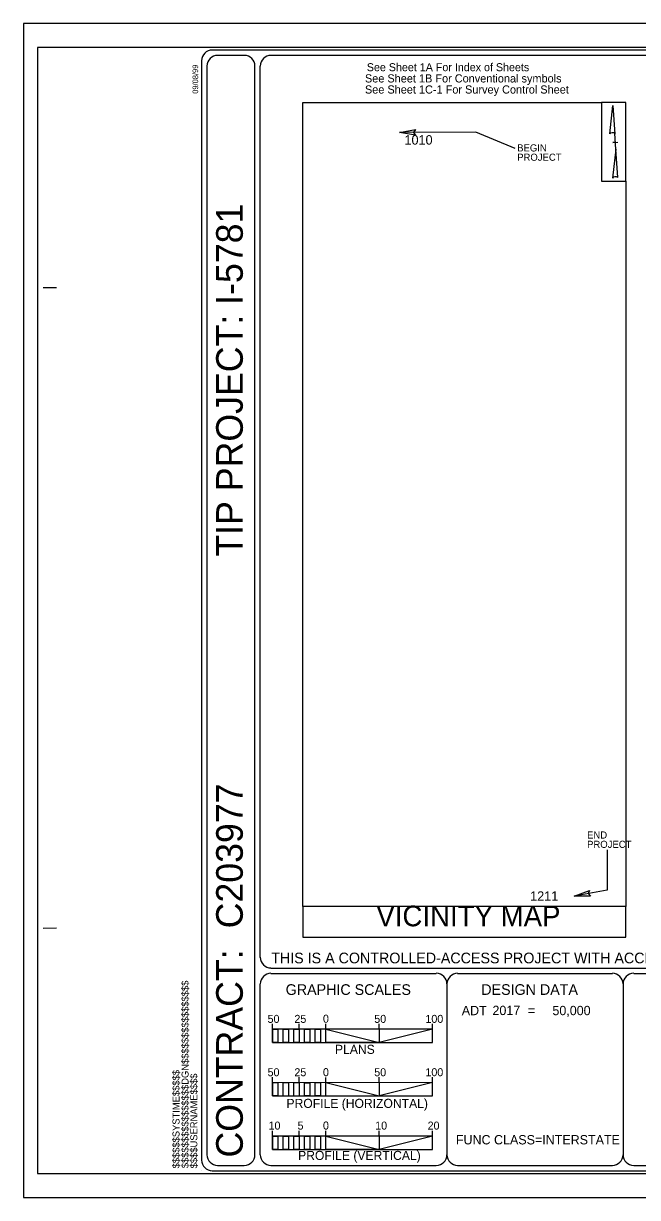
# Model space of a CAD drawing. Extents: x 2128934 to 2134034, y 641595 to 644895.
# Drawn here: x 2128934 to 2130661, y 641595 to 644895 of the extents above; entities that cross this region are included whole.
import ezdxf

# ---------------------------------------------------------------- set-up
doc = ezdxf.new("R2010")
doc.units = 0
for name, color, linetype in [('Default', 7, 'Continuous'), ('Prop DSN Text', 7, 'Continuous'), ('Prop Terminator CELL', 7, 'Continuous'), ('Sheet Data Field CELL', 7, 'Continuous'), ('Sheet Plot Border Inside CELL', 7, 'Continuous'), ('Sheet Plot Border Outside CELL', 7, 'Continuous'), ('Sheet Title CELL', 7, 'Continuous')]:
    doc.layers.add(name, color=color, linetype=linetype)

msp = doc.modelspace()

# ---------------------------------------------------------------- linework, layer by layer
at = {"layer": 'Default'}
for p, q in [((2130582.5, 644585.1), (2130591.1, 644664.5)), ((2130591.2, 644664.6), (2130591.1, 644664.5)), ((2130591.2, 644664.6), (2130591.1, 644664.5)), ((2130591.2, 644664.6), (2130596.6, 644583.6)), ((2130591.3, 644560.8), (2130591.2, 644560.8)), ((2130597.3, 644561.2), (2130591.3, 644560.8)), ((2130591.4, 644560.8), (2130605, 644561.7)), ((2130599.4, 644541.6), (2130596.4, 644586)), ((2130596.6, 644583.6), (2130596.5, 644585.9)), ((2130599.4, 644541.6), (2130590.6, 644460.7)), ((2130604.8, 644462), (2130599.4, 644541.6))]:
    msp.add_line(p, q, dxfattribs=at)
for centre, start_param, end_param in [((2130589.5, 644584.8), 0.216388, 2.908219), ((2130597.8, 644460.9), 0.201328, 3.141593)]:
    msp.add_ellipse(centre, major_axis=(7.17, 0.43), ratio=0.461098, start_param=start_param, end_param=end_param, dxfattribs=at)
at = {"layer": 'Prop DSN Text'}
for points in [[(2129719, 644673.4), (2130559.4, 644673.4), (2130559.4, 644673.4), (2130559.4, 644451.9), (2130627.9, 644451.9), (2130627.9, 642413.2), (2129719, 642413.2)], [(2130627.9, 644673.4), (2130559.4, 644673.4), (2130559.4, 644451.9), (2130627.9, 644451.9)], [(2129719, 642326.7), (2130627.9, 642326.7), (2130627.9, 642413.2), (2129719, 642413.2)]]:
    msp.add_lwpolyline(points, close=True, dxfattribs=at)
for points in [[(2130316.6, 644544), (2130205.7, 644589.7), (2129991.4, 644588.4)], [(2130575.7, 642572.4), (2130575.7, 642459.2), (2130482.9, 642442.1)]]:
    msp.add_lwpolyline(points, dxfattribs=at)
at = {"layer": 'Prop Terminator CELL'}
for points in [[(2130036.4, 644581), (2129991.4, 644588.4), (2130036.6, 644596.7), (2130030.9, 644588.7)], [(2130528.6, 642442.6), (2130482.9, 642442.1), (2130526, 642458.2), (2130521.7, 642449.2)]]:
    msp.add_lwpolyline(points, close=True, dxfattribs=at)
at = {"layer": 'Sheet Data Field CELL'}
for p, q in [((2129634.3, 642068), (2129634.3, 642083)), ((2129709.3, 642068), (2129709.3, 642083)), ((2129934.3, 642068), (2129934.3, 642083)), ((2130084.3, 642068), (2130084.3, 642083)), ((2129434.8, 641670.2), (2129434.8, 641670.2))]:
    msp.add_line(p, q, dxfattribs=at)
at = {"layer": 'Sheet Plot Border Inside CELL'}
msp.add_lwpolyline([(2128972.8, 641662.5), (2133972.3, 641662.5), (2133972.3, 644827.8), (2128972.8, 644827.8)], close=True, dxfattribs=at)
at = {"layer": 'Sheet Plot Border Outside CELL'}
msp.add_lwpolyline([(2128933.8, 641595.1), (2134033.8, 641595.1), (2134033.8, 644895.1), (2128933.8, 644895.1)], close=True, dxfattribs=at)
at = {"layer": 'Sheet Title CELL'}
for p, q in [((2129584.8, 641715.2), (2129584.8, 644775.2)), ((2129599.8, 642270.2), (2129599.8, 644775.2)), ((2128989.3, 644152.6), (2129026.8, 644152.6)), ((2128989.3, 644152.6), (2129026.8, 644152.6)), ((2128989.3, 642352.6), (2129026.8, 642352.7)), ((2128989.3, 642352.6), (2129026.8, 642352.7)), ((2129629.8, 642240.2), (2133889.8, 642240.2)), ((2129629.8, 642225.1), (2130094.8, 642225.2)), ((2130154.8, 642225.1), (2130589.8, 642225.2)), ((2130649.8, 642225.1), (2131789.8, 642225.1)), ((2129599.8, 641715.1), (2129599.8, 642195.2)), ((2130124.8, 642195.2), (2130124.8, 641715.1)), ((2130619.8, 642195.2), (2130619.8, 641715.2)), ((2129634.3, 642068), (2129634.3, 642082.9)), ((2129634.3, 642082.9), (2129634.3, 642082.9)), ((2129709.3, 642067.9), (2129709.3, 642083)), ((2129784.3, 642067.9), (2129784.3, 642082.9)), ((2129934.3, 642068), (2129934.3, 642082.9)), ((2130084.3, 642068), (2130084.3, 642083)), ((2129634.3, 642068), (2129634.3, 642030.5)), ((2129634.3, 642068), (2129634.3, 642068)), ((2130084.3, 642068), (2129634.3, 642068)), ((2129739.3, 642068), (2129739.3, 642030.5)), ((2129934.3, 642068), (2129934.3, 642030.5)), ((2130084.3, 642030.4), (2130084.3, 642068)), ((2129634.3, 642030.5), (2130084.3, 642030.4)), ((2129634.3, 641917.9), (2129634.3, 641933)), ((2129634.3, 641917.9), (2129634.3, 641933)), ((2129634.3, 641933), (2129634.3, 641933)), ((2130084.3, 641918), (2129634.3, 641917.9)), ((2130084.3, 641918), (2129634.3, 641917.9)), ((2129634.3, 641917.9), (2129634.3, 641880.5)), ((2129634.3, 641917.9), (2129634.3, 641917.9)), ((2129634.3, 641917.9), (2129634.3, 641917.9)), ((2129709.3, 641917.9), (2129709.3, 641933)), ((2129709.3, 641917.9), (2129709.3, 641933)), ((2129739.3, 641917.9), (2129739.3, 641880.5)), ((2129784.3, 641918), (2129784.3, 641932.9)), ((2129784.3, 641918), (2129784.3, 641932.9)), ((2129934.3, 641918), (2129934.3, 641933)), ((2129934.3, 641918), (2129934.3, 641933)), ((2129934.3, 641918), (2129934.3, 641880.5)), ((2130084.3, 641918), (2130084.3, 641933)), ((2130084.3, 641918), (2130084.3, 641933)), ((2130084.3, 641880.5), (2130084.3, 641918)), ((2129634.3, 641880.5), (2130084.3, 641880.5)), ((2129634.3, 641767.9), (2129634.3, 641783)), ((2129634.3, 641767.9), (2129634.3, 641783)), ((2129634.3, 641767.9), (2129634.3, 641783)), ((2129634.3, 641783), (2129634.3, 641783)), ((2130084.3, 641768), (2129634.3, 641767.9)), ((2130084.3, 641768), (2129634.3, 641767.9)), ((2130084.3, 641768), (2129634.3, 641767.9)), ((2129634.3, 641767.9), (2129634.3, 641730.5)), ((2129634.3, 641767.9), (2129634.3, 641767.9)), ((2129634.3, 641767.9), (2129634.3, 641767.9)), ((2129634.3, 641767.9), (2129634.3, 641767.9)), ((2129709.3, 641768), (2129709.3, 641782.9)), ((2129709.3, 641768), (2129709.3, 641782.9)), ((2129709.3, 641768), (2129709.3, 641782.9)), ((2129739.3, 641767.9), (2129739.3, 641730.4)), ((2129784.3, 641768), (2129784.3, 641782.9)), ((2129784.3, 641768), (2129784.3, 641782.9)), ((2129784.3, 641768), (2129784.3, 641782.9)), ((2129934.3, 641767.9), (2129934.3, 641783)), ((2129934.3, 641767.9), (2129934.3, 641783)), ((2129934.3, 641767.9), (2129934.3, 641783)), ((2129934.3, 641767.9), (2129934.3, 641730.4)), ((2130084.3, 641768), (2130084.3, 641782.9)), ((2130084.3, 641768), (2130084.3, 641782.9)), ((2130084.3, 641768), (2130084.3, 641782.9)), ((2130084.3, 641730.5), (2130084.3, 641768)), ((2129634.3, 641730.5), (2130084.3, 641730.5)), ((2129434.8, 641670.2), (2129434.8, 641670.2)), ((2129434.8, 641670.2), (2129434.8, 641670.2)), ((2129434.8, 641670.2), (2129434.8, 641670.2)), ((2129434.8, 641670.2), (2129434.8, 641670.2))]:
    msp.add_line(p, q, dxfattribs=at)
for points in [[(2133904.8, 644820.1), (2129464.7, 644820.2)], [(2129434.8, 644790.2), (2129434.8, 641700.2)], [(2129434.8, 644790.2), (2129434.8, 641700.2)], [(2129554.8, 644805.1), (2129479.8, 644805.2)], [(2133889.8, 644805.1), (2129629.8, 644805.1)], [(2129449.8, 644775.2), (2129449.8, 641715.2)], [(2129479.7, 641685.2), (2129554.8, 641685.2)], [(2129629.8, 641685.1), (2130094.8, 641685.2)], [(2130154.8, 641685.2), (2130589.8, 641685.2)], [(2130649.8, 641685.1), (2131789.8, 641685.1)], [(2129464.8, 641670.1), (2133904.8, 641670.1)]]:
    msp.add_lwpolyline(points, dxfattribs=at)
for points in [[(2129634.3, 642068), (2129649.3, 642068), (2129649.3, 642030.5), (2129634.3, 642030.5)], [(2129664.3, 642068), (2129679.3, 642067.9), (2129679.3, 642030.4), (2129664.3, 642030.4)], [(2129694.3, 642067.9), (2129709.3, 642067.9), (2129709.3, 642030.5), (2129694.3, 642030.5)], [(2129724.3, 642067.9), (2129739.3, 642068), (2129739.3, 642030.5), (2129724.3, 642030.5)], [(2129754.3, 642068), (2129769.3, 642068), (2129769.3, 642030.4), (2129754.3, 642030.5)], [(2129784.3, 642067.9), (2129934.3, 642030.5), (2129784.3, 642030.4)], [(2130084.3, 642068), (2129934.3, 642030.5), (2130084.3, 642030.4)], [(2129634.3, 641917.9), (2129649.3, 641918), (2129649.3, 641880.5), (2129634.3, 641880.5)], [(2129664.3, 641918), (2129679.3, 641918), (2129679.3, 641880.4), (2129664.3, 641880.5)], [(2129694.3, 641918), (2129709.3, 641917.9), (2129709.3, 641880.5), (2129694.3, 641880.4)], [(2129724.3, 641917.9), (2129739.3, 641917.9), (2129739.3, 641880.5), (2129724.3, 641880.5)], [(2129754.3, 641918), (2129769.3, 641918), (2129769.3, 641880.5), (2129754.3, 641880.5)], [(2129784.3, 641918), (2129934.3, 641880.5), (2129784.3, 641880.4)], [(2130084.3, 641918), (2129934.3, 641880.5), (2130084.3, 641880.5)], [(2129634.3, 641767.9), (2129649.3, 641767.9), (2129649.3, 641730.4), (2129634.3, 641730.5)], [(2129664.3, 641768), (2129679.3, 641768), (2129679.3, 641730.5), (2129664.3, 641730.5)], [(2129694.3, 641768), (2129709.3, 641768), (2129709.3, 641730.4), (2129694.3, 641730.5)], [(2129724.3, 641767.9), (2129739.3, 641767.9), (2129739.3, 641730.4), (2129724.3, 641730.5)], [(2129754.3, 641767.9), (2129769.3, 641768), (2129769.3, 641730.5), (2129754.3, 641730.5)], [(2129784.3, 641768), (2129934.3, 641730.4), (2129784.3, 641730.5)], [(2130084.3, 641768), (2129934.3, 641730.4), (2130084.3, 641730.5)]]:
    msp.add_lwpolyline(points, close=True, dxfattribs=at)
for centre, start, end in [((2129464.8, 644790.3), 90, 180), ((2129479.8, 644775.3), 90, 180), ((2129554.8, 644775.3), 0, 90), ((2129629.8, 644775.3), 90, 180), ((2129629.8, 642270.3), 180, 270), ((2129629.8, 642195.3), 90, 180), ((2130094.8, 642195.3), 0, 90), ((2130154.8, 642195.3), 90, 180), ((2130589.8, 642195.3), 0, 90), ((2130649.8, 642195.3), 90, 180), ((2129464.8, 641700.3), 180, 270), ((2129479.8, 641715.3), 180, 270), ((2129554.8, 641715.3), 270, 360), ((2129629.8, 641715.3), 180, 270), ((2130094.8, 641715.3), 270, 360), ((2130154.8, 641715.3), 180, 270), ((2130589.8, 641715.3), 270, 360), ((2130649.8, 641715.3), 180, 270)]:
    msp.add_arc(centre, 30, start, end, dxfattribs=at)

# ---------------------------------------------------------------- texts
at = {"layer": 'Default'}
for s, p in [('See Sheet 1B For Conventional symbols', (2129894.1, 644729.3)), ('See Sheet 1C-1 For Survey Control Sheet', (2129894.1, 644698.1))]:
    msp.add_text(s, height=22.956, rotation=0.0001, dxfattribs=at).set_placement(p)
for s, p in [('1010', (2130005.3, 644554.7)), ('1211', (2130358.7, 642429.2))]:
    msp.add_text(s, height=26.54, dxfattribs=at).set_placement(p)
at = {"layer": 'Prop DSN Text'}
for s, height, p in [('BEGIN ', 20, (2130322.2, 644535.4)), ('PROJECT', 20, (2130322.2, 644509.2)), ('END ', 20, (2130518.7, 642604.1)), ('PROJECT', 20, (2130518.7, 642577.9)), ('THIS IS A CONTROLLED-ACCESS PROJECT WITH ACCESS BEING LIMITED TO INTERCHANGES.', 30, (2129630.5, 642253.4))]:
    msp.add_text(s, height=height, dxfattribs=at).set_placement(p)
msp.add_text('VICINITY MAP', height=58.061, rotation=359.9999, dxfattribs=at).set_placement((2129926.2, 642357.5))
at = {"layer": 'Sheet Data Field CELL'}
for s, height, p in [('ADT', 26.25, (2130166.4, 642107.6)), ('=', 26.3, (2130352.3, 642107.7)), ('FUNC CLASS=INTERSTATE', 26.25, (2130149.8, 641744.4))]:
    msp.add_text(s, height=height, rotation=360, dxfattribs=at).set_placement(p)
for s, height, p in [('2017', 26.25, (2130252.7, 642107.9)), ('50,000   ', 26.25, (2130421.3, 642107.6)), ('50', 22.5, (2129620.3, 642086)), ('25', 22.5, (2129695.7, 642086)), ('50', 22.5, (2129920.3, 642086)), ('100', 22.5, (2130064.1, 642086)), ('50', 22.5, (2129620.3, 641936)), ('25', 22.5, (2129695.7, 641936)), ('50', 22.5, (2129920.3, 641936)), ('100', 22.5, (2130064.1, 641936)), ('10', 22.5, (2129623, 641786)), ('5', 22.5, (2129704.6, 641786)), ('10', 22.5, (2129922.9, 641786)), ('20', 22.5, (2130070.3, 641786))]:
    msp.add_text(s, height=height, dxfattribs=at).set_placement(p)
at = {"layer": 'Sheet Title CELL'}
for s, height, rotation, p in [('09/08/99', 15.75, 90, (2129425, 644697.5)), ('See Sheet 1A For Index of Sheets', 22.5, 360, (2129899.4, 644761)), ('TIP PROJECT: I-5781', 75, 90, (2129550.6, 643396.6)), ('C203977   ', 75, 90, (2129550.6, 642351.7)), ('CONTRACT:', 75, 90, (2129550.6, 641707.5)), ('$$$$$$$$$$$$$$$$DGN$$$$$$$$$$$$$$$$', 19.687, 90, (2129398.1, 641677.7)), ('GRAPHIC SCALES', 29.999, 360, (2129671.2, 642164.6)), ('DESIGN DATA', 29.999, 360, (2130221.2, 642164.7)), ('0', 22.5, 360, (2129776, 642086.4)), ('PLANS', 25.5, 360, (2129809.8, 641998.9)), ('$$$$$$SYSTIME$$$$$', 19.687, 90, (2129372.6, 641676.9)), ('0', 22.5, 360, (2129776, 641936.4)), ('0', 22.5, 360, (2129776, 641936)), ('$$$$USERNAME$$$$', 19.687, 90, (2129422.7, 641677.2)), ('PROFILE (HORIZONTAL)', 25.499, 360, (2129673.4, 641847)), ('0', 22.5, 360, (2129776, 641786.4)), ('0', 22.5, 360, (2129776, 641786)), ('0', 22.5, 360, (2129776, 641786)), ('PROFILE (VERTICAL)', 25.499, 360, (2129706.1, 641700.7))]:
    msp.add_text(s, height=height, rotation=rotation, dxfattribs=at).set_placement(p)

doc.saveas('drawing.dxf')
